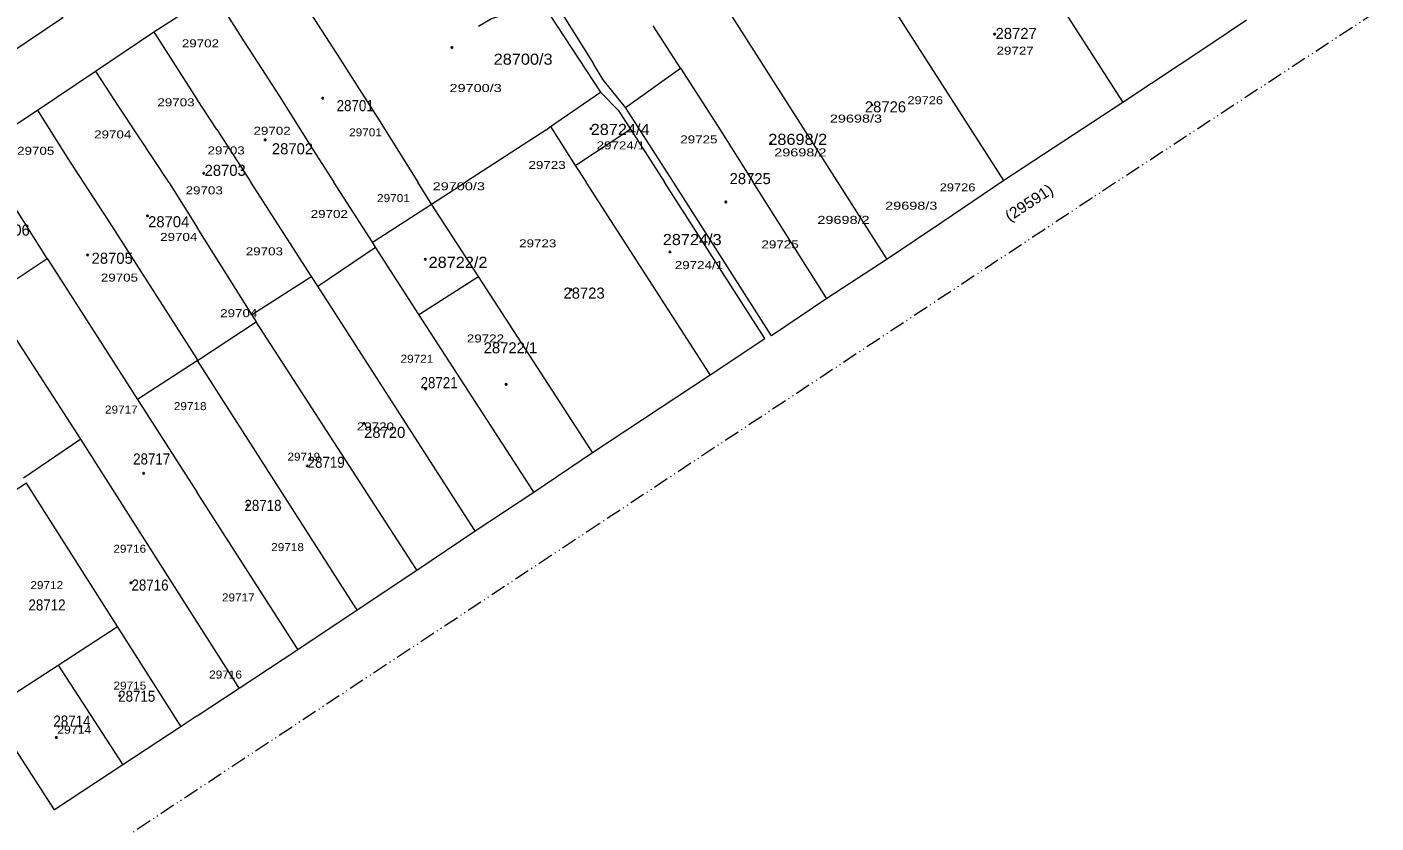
# Model space of a CAD drawing. Extents: x 650553 to 652508, y 239277 to 241647.
# Drawn here: x 652069.7 to 652508.1, y 240541.9 to 240800.4 of the extents above; entities that cross this region are included whole.
import ezdxf

# ---------------------------------------------------------------- set-up
doc = ezdxf.new("R2010")
doc.units = 0
doc.header["$PDMODE"] = 32
doc.header["$PDSIZE"] = 0.5
doc.linetypes.add('DASH_DOUBLE_DOT', pattern=[9.2, 5, -1.2, 0.3, -1.2, 0.3, -1.2])
for name, color, linetype in [('19', 7, 'Continuous'), ('20', 7, 'Continuous'), ('6', 7, 'Continuous')]:
    doc.layers.add(name, color=color, linetype=linetype)
for name, color, linetype, lineweight in [('3', 7, 'Continuous', 13), ('5', 7, 'Continuous', 13), ('52', 7, 'DASH_DOUBLE_DOT', 13)]:
    doc.layers.add(name, color=color, linetype=linetype, lineweight=lineweight)

msp = doc.modelspace()

# ---------------------------------------------------------------- linework, layer by layer
at = {"layer": '3'}
msp.add_line((652279.77, 240749.99), (652264.23, 240774.31), dxfattribs=at)
for points in [[(652029.04, 240821.24), (652049.7, 240839.74), (652081.4, 240803.43), (652058.39, 240788.05)], [(652234.25, 240819.2), (652237.6, 240813.95), (652240.89, 240808.97), (652253.77, 240788.47)], [(652130.48, 240811.26), (652125, 240807.76), (652110.91, 240798.75), (652092.01, 240785.99), (652073.09, 240773.31), (652053.84, 240760.57)], [(652216.49, 240800.66), (652220.68, 240803.17), (652237.25, 240807.92), (652256.07, 240779.29)], [(652466.09, 240802.6), (652453.76, 240794.42), (652425.84, 240775.91), (652387.13, 240750.57)], [(652264.23, 240774.31), (652256.94, 240783.26), (652253.77, 240788.47)], [(652256.07, 240779.29), (652261.82, 240773.41), (652265.795, 240767.229), (652276.88, 240749.99)], [(652291.69, 240687.47), (652309.5, 240699.23), (652276.88, 240749.99)], [(652329.7, 240712.17), (652311.63, 240700.11), (652279.77, 240749.99)], [(652387.13, 240750.57), (652366.98, 240736.86), (652349.23, 240724.96), (652329.7, 240712.17)], [(652125, 240576.63), (652138.66, 240585.65), (652157.74, 240598.25), (652177.03, 240611.06), (652196.37, 240623.98), (652215.37, 240636.71), (652234.45, 240649.31), (652253.45, 240662.22), (652291.69, 240687.47)], [(652100.82, 240560.71), (652078.69, 240546.12), (652057.49, 240578.77)], [(652125, 240576.63), (652119.77, 240573.18), (652100.82, 240560.71)]]:
    msp.add_lwpolyline(points, dxfattribs=at)
at = {"layer": '5'}
for p, q in [((652387.13, 240750.57), (652342.803, 240819.836)), ((652282.14, 240787.08), (652273.23, 240800.78)), ((652124.93, 240777), (652125, 240776.9)), ((652131.36, 240767.14), (652125, 240776.9)), ((652131.36, 240767.14), (652142.41, 240750)), ((652238.33, 240766.86), (652212.24, 240749.99)), ((652201.21, 240742.86), (652196.75, 240749.99)), ((652201.21, 240742.86), (652212.24, 240749.99)), ((652164.25, 240716.24), (652182.93, 240728.91)), ((652125, 240692.02), (652105.61, 240679.39)), ((652105.61, 240679.39), (652125, 240649.21)), ((652079.86, 240593.13), (652100.82, 240560.71))]:
    msp.add_line(p, q, dxfattribs=at)
for points in [[(652381.13, 240845.574), (652425.519, 240776.41), (652425.84, 240775.91)], [(652149.53, 240824.07), (652149.852, 240823.57), (652171.52, 240789.92), (652174.3, 240785.49), (652184.49, 240769.61), (652196.75, 240749.99)], [(652130.48, 240811.26), (652130.794, 240810.76), (652140.3, 240795.6), (652144.73, 240788.82), (652151.66, 240778.03), (652162.65, 240760.59), (652169.47, 240750)], [(652349.23, 240724.96), (652348.911, 240725.46), (652293.291, 240812.764), (652292.972, 240813.264)], [(652110.91, 240798.75), (652111.232, 240798.25), (652124.93, 240777)], [(652092.01, 240785.99), (652092.337, 240785.49), (652099.37, 240774.74), (652105.76, 240765.07), (652115.71, 240750)], [(652264.23, 240774.31), (652282.14, 240787.08), (652294.21, 240768.24), (652305.76, 240749.98)], [(652238.33, 240766.86), (652239.8, 240768.04), (652256.07, 240779.29)], [(652073.09, 240773.31), (652073.407, 240772.81), (652082.77, 240758.06), (652088.01, 240750)], [(652239.8, 240768.04), (652247.912, 240755.439), (652251.42, 240749.99)], [(652247.912, 240755.439), (652248.412, 240755.769), (652265.295, 240766.899), (652265.795, 240767.229)], [(652076.22, 240725.27), (652054.157, 240760.07), (652053.84, 240760.57)], [(652088.01, 240750), (652096.54, 240736.88), (652125, 240692.39)], [(652115.71, 240750), (652115.88, 240749.74), (652125, 240735.27)], [(652164.25, 240716.24), (652162.18, 240719.34), (652142.41, 240750)], [(652182.93, 240728.91), (652182.01, 240730.53), (652169.47, 240750)], [(652291.69, 240687.47), (652291.368, 240687.97), (652251.42, 240749.99)], [(652329.7, 240712.17), (652329.383, 240712.67), (652305.76, 240749.98)], [(652182.01, 240730.53), (652182.51, 240730.851), (652201.21, 240742.86)], [(652253.45, 240662.22), (652253.126, 240662.72), (652216.407, 240719.402), (652201.21, 240742.86)], [(652144.24, 240704.65), (652144.32, 240704.65), (652142.77, 240707.06), (652125, 240735.27)], [(652234.45, 240649.31), (652234.126, 240649.81), (652197.067, 240707.068), (652182.93, 240728.91)], [(652087.23, 240666.57), (652057.31, 240712.66), (652076.22, 240725.27)], [(652076.22, 240725.27), (652078.43, 240721.83), (652105.61, 240679.39)], [(652142.77, 240707.06), (652143.27, 240707.376), (652161.68, 240719.024), (652162.18, 240719.34)], [(652197.067, 240707.068), (652197.567, 240707.387), (652215.907, 240719.083), (652216.407, 240719.402)], [(652215.37, 240636.71), (652215.049, 240637.21), (652164.25, 240716.24)], [(652125, 240692.02), (652125.167, 240692.129), (652144.24, 240704.65)], [(652196.37, 240623.98), (652196.047, 240624.48), (652144.24, 240704.65)], [(652177.03, 240611.06), (652176.71, 240611.56), (652125.167, 240692.129), (652125, 240692.39)], [(652125, 240607.14), (652087.23, 240666.57), (652068.55, 240653.87)], [(652057.49, 240578.77), (652079.86, 240593.13), (652099.1, 240605.65), (652069.57, 240652.28), (652049.84, 240639.46)], [(652157.74, 240598.25), (652157.419, 240598.75), (652125, 240649.21)], [(652119.77, 240573.18), (652119.452, 240573.68), (652099.1, 240605.65)], [(652138.66, 240585.65), (652138.342, 240586.15), (652125, 240607.14)]]:
    msp.add_lwpolyline(points, dxfattribs=at)
at = {"layer": '52'}
for points in [[(652508.14, 240805.294), (652415.96, 240744.924), (652255.621, 240638.986), (652125.045, 240552.683)], [(652125.045, 240552.683), (652045.248, 240499.833), (651901.888, 240405.32), (651851.361, 240359.263), (651750.052, 240268.782)]]:
    msp.add_lwpolyline(points, dxfattribs=at)
at = {"layer": '6'}
for p in [(652384.174, 240798.072), (652207.799, 240793.765), (652165.838, 240777.3), (652344.359, 240775.1), (652252.972, 240767.364), (652147.102, 240763.75), (652311.439, 240762.717), (652127.165, 240752.905), (652296.829, 240743.595), (652108.868, 240739.059), (652278.717, 240727.349), (652089.406, 240726.35), (652199.144, 240724.964), (652246.524, 240715.13), (652225.438, 240684.356), (652199.253, 240682.81), (652179.232, 240671.66), (652160.786, 240657.855), (652107.638, 240655.46), (652141.39, 240645.189), (652103.499, 240619.875), (652099.849, 240583.18), (652079.242, 240569.625)]:
    msp.add_point(p, dxfattribs=at)

# ---------------------------------------------------------------- texts
at = {"layer": '19'}
for s, p in [('28727', (652384.493, 240796.509)), ('28726', (652342.018, 240772.68)), ('28702', (652149.296, 240759.061)), ('28703', (652127.427, 240752.057)), ('28725', (652298.056, 240749.362)), ('28706', (652057.232, 240732.659)), ('28704', (652109.067, 240735.353)), ('28705', (652090.709, 240723.499)), ('28723', (652244.06, 240712.184)), ('28722/1', (652218.141, 240694.403)), ('28720', (652179.263, 240666.923))]:
    msp.add_text(s, height=3.6, dxfattribs=at).set_placement(p)
for s, width, p in [('28700/3', 1.1, (652221.381, 240788.158)), ('28701', 0.9, (652170.353, 240773.071)), ('28724/4', 1.1, (652252.908, 240765.34)), ('28698/2', 1.1, (652310.631, 240762.118)), ('28724/3', 1.1, (652276.335, 240729.566)), ('28722/2', 1.1, (652200.224, 240722.177)), ('28721', 0.9, (652197.623, 240683.088)), ('28717', 0.9, (652104.209, 240658.301)), ('28719', 0.9, (652160.905, 240657.224)), ('28718', 0.9, (652140.386, 240643.214)), ('28716', 0.9, (652103.669, 240617.351)), ('28712', 0.9, (652070.191, 240610.885)), ('28715', 0.9, (652099.35, 240581.249)), ('28714', 0.9, (652078.29, 240573.167))]:
    msp.add_text(s, height=3.6, dxfattribs=dict(at, width=width)).set_placement(p)
at = {"layer": '19', "width": 1.05}
msp.add_text('(29591)', height=3.6, rotation=33.209, dxfattribs=at).set_placement((652389.059, 240737.08))
at = {"layer": '20'}
for s, width, p in [('29702', 1.25, (652120.037, 240793.81)), ('29727', 1.25, (652384.817, 240791.427)), ('29700/3', 1.35, (652207.03, 240779.283)), ('29703', 1.25, (652112.078, 240774.646)), ('29726', 1.2, (652355.833, 240775.323)), ('29698/3', 1.35, (652330.634, 240769.364)), ('29702', 1.25, (652143.324, 240765.407)), ('29701', 1.1, (652174.4, 240764.886)), ('29704', 1.25, (652091.534, 240764.226)), ('29724/1', 1.25, (652254.835, 240760.662)), ('29725', 1.25, (652282.023, 240762.605)), ('29705', 1.25, (652066.496, 240758.902)), ('29703', 1.25, (652128.385, 240759.025)), ('29698/2', 1.35, (652312.553, 240758.382)), ('29723', 1.25, (652232.692, 240754.282)), ('29700/3', 1.35, (652201.563, 240747.377)), ('29726', 1.2, (652366.328, 240747.027)), ('29703', 1.25, (652121.258, 240746.061)), ('29701', 1.1, (652183.485, 240743.534)), ('29702', 1.25, (652161.912, 240738.372)), ('29698/3', 1.35, (652348.609, 240741.063)), ('29698/2', 1.35, (652326.588, 240736.466)), ('29704', 1.25, (652112.983, 240730.921)), ('29703', 1.25, (652140.819, 240726.249)), ('29723', 1.25, (652229.659, 240728.847)), ('29725', 1.25, (652308.412, 240728.504)), ('29724/1', 1.25, (652280.242, 240721.779)), ('29705', 1.25, (652093.711, 240717.715)), ('29704', 1.25, (652132.486, 240706.16)), ('29722', 1.25, (652212.662, 240697.936)), ('29721', 1.1, (652191.118, 240691.358)), ('29717', 1.1, (652095.051, 240674.849)), ('29718', 1.1, (652117.428, 240675.965)), ('29720', 1.25, (652176.9, 240669.369)), ('29719', 1.1, (652154.351, 240659.539)), ('29716', 1.1, (652097.775, 240629.637)), ('29718', 1.1, (652149.075, 240630.171)), ('29712', 1.1, (652070.819, 240617.827)), ('29717', 1.1, (652133.073, 240613.836)), ('29715', 1.1, (652097.827, 240585.186)), ('29716', 1.1, (652128.915, 240588.779)), ('29714', 1.15, (652079.511, 240570.865))]:
    msp.add_text(s, height=2.6, dxfattribs=dict(at, width=width)).set_placement(p)

doc.saveas('drawing.dxf')
